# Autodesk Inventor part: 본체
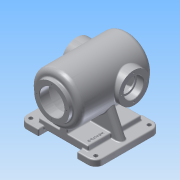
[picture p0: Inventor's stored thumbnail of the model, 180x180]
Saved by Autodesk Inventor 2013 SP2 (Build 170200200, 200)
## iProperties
Created: 2013-06
Part Number: 본체
Document SubType Name: Modeling
Designer: SeoGD™[esajin.kr]
Density: 2.71 g/cm^3
Material: 알루미늄 6061
Mass: 4578.67 g
Surface Area: 2686.6 cm^2
Volume: 1689.54 cm^3
Author: SeoGD™[esajin.kr]
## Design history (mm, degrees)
sketch "스케치1"
  geometry: L1 (-100, 85)-(-50, 85); L2 (-50, 85)-(-50, -85); L3 (-50, -85)-(-100, -85); L4 (-100, -85)-(-100, 85); L5 (50, 85)-(100, 85); L6 (100, 85)-(100, -85); L7 (100, -85)-(50, -85); L8 (50, -85)-(50, 85); 3 further points
  constraints: 16 end point, 4 parallel, 2 equal length, 2 horizontal, 2 horizontal alignment, 2 midpoint, 2 perpendicular
  dimensions: "d0" = 100 distance between parallel lines of L8 L2; "d1" = 170 distance of L3.end L1.start; "d3" = 200 distance between parallel lines of L6 L4; "d4" = 50 distance from line of point (0, 0) L2 (= 0.5 x d0)
extrude "돌출1" new body sketch "스케치1" distance "d5" = 16; taper "d6" = 0 deg
node "작업 평면1"
sketch "스케치2"
  geometry: L1 (-65, 70)-(65, 70); L2 (65, 70)-(65, -70); L3 (65, -70)-(-65, -70); L4 (-65, -70)-(-65, 70); 3 further points
  constraints: 8 end point, 2 midpoint, 2 parallel, 1 horizontal, 1 horizontal alignment, 1 perpendicular, 1 vertical alignment
  dimensions: "d8" = 130 distance of L2.end L3.end; "d9" = 140 distance of L1.end L2.end
extrude "돌출2" join sketch "스케치2" distance "d10" = 20; taper "d11" = 0 deg
sketch "스케치3"
  geometry: L1 (-100, 110)-(100, 110); L2 (85, 0)-(-85, 0) reference; L3 (100, 110)-(100, 175); L4 (100, 175)-(-90, 175); L5 (-90, 175)-(-90, 156); L6 (-90, 156)-(-100, 156); L7 (-100, 156)-(-100, 110); L8 (90, 110)-(90, 165); L9 (90, 165)-(-75, 165); L10 (-75, 165)-(-75, 110); L11 (-100, 142.5)-(-75, 142.5); 3 further points
  constraints: 20 end point, 5 perpendicular, 4 parallel, 4 point on line, 2 midpoint, 1 horizontal, 1 vertical alignment
  dimensions: "d12" = 110 distance from line of L2 L1.end; "d13" = 200 distance of L1.start L1.end; "d14" = 130 diameter of L4 L1; "d15" = 92 diameter of L6 L1; "d16" = 10 distance of L5.end L6.end; "d42" = 110 diameter of L9 L1; "d43" = 10 distance between parallel lines of L3 L8; "d44" = 25 distance between parallel lines of L10 L7; "d45" = 65 diameter of L11 L1
revolve "회전1" sketch "스케치3" stored, may be unused: angle "d17" = 90 deg
sketch "스케치4"
  geometry: L1 (-50, 70)-(50, 70) reference; L2 (50, -70)-(-50, -70) reference; L3 (-10, 70)-(-10, -70); L4 (10, -70)-(10, 70); 1 further point
  constraints: 4 end point, 4 point on line, 2 perpendicular
  dimensions: "d18" = 20 distance between parallel lines of L4 L3; "d19" = 10 distance from line of point (0, 0) L3
extrude "돌출3" join sketch "스케치4" stored distance "d20" = 10; taper "d21" = 0 deg
node "작업 평면2"
sketch "스케치5"
  geometry: L1 (-50, -8)-(0, -8) reference; L2 (100, -8)-(150, -8) reference; L3 (-40, -8)-(-8.943, -74.601); L4 (140, -8)-(108.943, -74.601); L5 (-50, 8)-(-50, -8) reference; L6 (150, 8)-(150, -8) reference; A1 r 65 centre (50, -102) between (-8.943, -74.601) and (108.943, -74.601) reference; 1 further point
  constraints: 4 end point, 2 point on circle, 2 point on line, 1 equal length
  dimensions: "d23" = 10 distance from line of L3.start L5; "d24" = 10 distance from line of L4.start L6; "d25" = 25 deg angle of L3 L5
feature "리브1" sketch "스케치5" dims "d26" = 1, "d27" = 20, "d28" = 0
node "작업 평면3"
sketch "스케치6"
  geometry: L1 (100, 156)-(100, 64) reference; C1 r 40 at (-40, 110); 2 further points
  constraints: 1 centre point, 1 horizontal alignment, 1 midpoint
  dimensions: "d37" = 80 diameter of C1; "d38" = 140 distance from line of C1.centre L1
extrude "돌출4" join sketch "스케치6" stored distance "d39" = 10; taper "d40" = 0 deg
hole "구멍1" diameter "d48" = 42; stored, may be unused: countersink angle "d52" = 90 deg, drill point angle "d54" = 118 deg; dims "d46" = 10, "d47" = 10, "d49" = 6, "d50" = 52, "d51" = 18, "d53" = 8
sketch "스케치7"
  geometry: C1 r 40 at (0, 0) reference; 2 further points
  constraints: 1 horizontal alignment
  dimensions: "d55" = 32.5 distance of point (32.5, 0) C1.centre
hole "구멍2" sketch "스케치7" at (32.5, 0) diameter "d56" = 3.242; stored, may be unused: countersink angle "d60" = 90 deg, drill point angle "d62" = 118 deg; dims "d57" = 10, "d58" = 52, "d59" = 18, "d61" = 13
sketch "스케치8"
  geometry: C1 r 46 at (0, 0) reference; 2 further points
  constraints: 1 vertical alignment
  dimensions: "d66" = 39 distance of C1.centre point (0, 39)
hole "구멍3" sketch "스케치8" at (0, 39) diameter "d67" = 3.242; stored, may be unused: countersink angle "d71" = 90 deg, drill point angle "d73" = 118 deg; dims "d68" = 10, "d69" = 52, "d70" = 18, "d72" = 13
fillet "모깎기7" dims "d77" = 20, "d78" = 13, "d79" = 3, "d80" = 10
fillet "모깎기8" dims "d81" = 3
fillet "모깎기9" dims "d82" = 3
fillet "모깎기10" dims "d83" = 3, "d84" = 0.3
chamfer "모따기1" distance "d85" = 1; stored, may be unused: second distance "d86" = 2, angle "d87" = 45 deg
node "작업 평면4"
sketch "스케치10"
  geometry: 5 further points
  constraints: 2 horizontal alignment, 2 vertical alignment
  dimensions: "d90" = 170 distance of point (85, 70) point (-85, 70); "d91" = 140 distance of point (-85, 70) point (-85, -70); "d92" = 70 vertical distance of point (0, 0) point (-85, -70) (= 0.5 x d91); "d93" = 85 horizontal distance of point (0, 0) point (-85, 70) (= 0.5 x d90)
hole "구멍4" sketch "스케치10" at (-85, 70), (85, 70), (85, -70), (-85, -70) diameter "d94" = 10; stored, may be unused: countersink angle "d98" = 90 deg, drill point angle "d100" = 118 deg; dims "d95" = 6, "d96" = 4, "d97" = 2, "d99" = 8
sketch "스케치11"
  geometry: L1 (13, -70)-(62, -70) reference; L2 (65, -67)-(65, -13) reference; 2 further points
  constraints: 1 other
  dimensions: "d101" = 30 distance from line of point (55, -40) L1; "d102" = 10 distance from line of point (55, -40) L2
feature "엠보싱2" sketch "스케치11" dims "d0" = 100, "d1" = 170, "d3" = 200, "d4" = 50 (= 0.5 x d0), "d103" = 1, "d104" = 0
node "솔리드1"
mirror "대칭1"
pattern_circular "원형 패턴1" dims angle "d64" = 360 deg
mirror "대칭3"
pattern_circular "원형 패턴2" dims angle "d75" = 360 deg
other parameters: "d7" = 8, "d36" = -75
